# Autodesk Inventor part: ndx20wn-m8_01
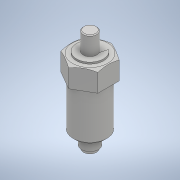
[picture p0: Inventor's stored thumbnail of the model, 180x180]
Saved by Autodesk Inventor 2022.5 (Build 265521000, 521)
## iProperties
Part Number: ndx20wn-m8_01
Material: 一般
Document SubType Name: Modeling
Designer: ImaoCorp
Density: 1 g/cm^3
Appearance: 既定
Author: ImaoCorp
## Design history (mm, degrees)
feature "ndx20wn-m8_01"
node "ソリッド1"
